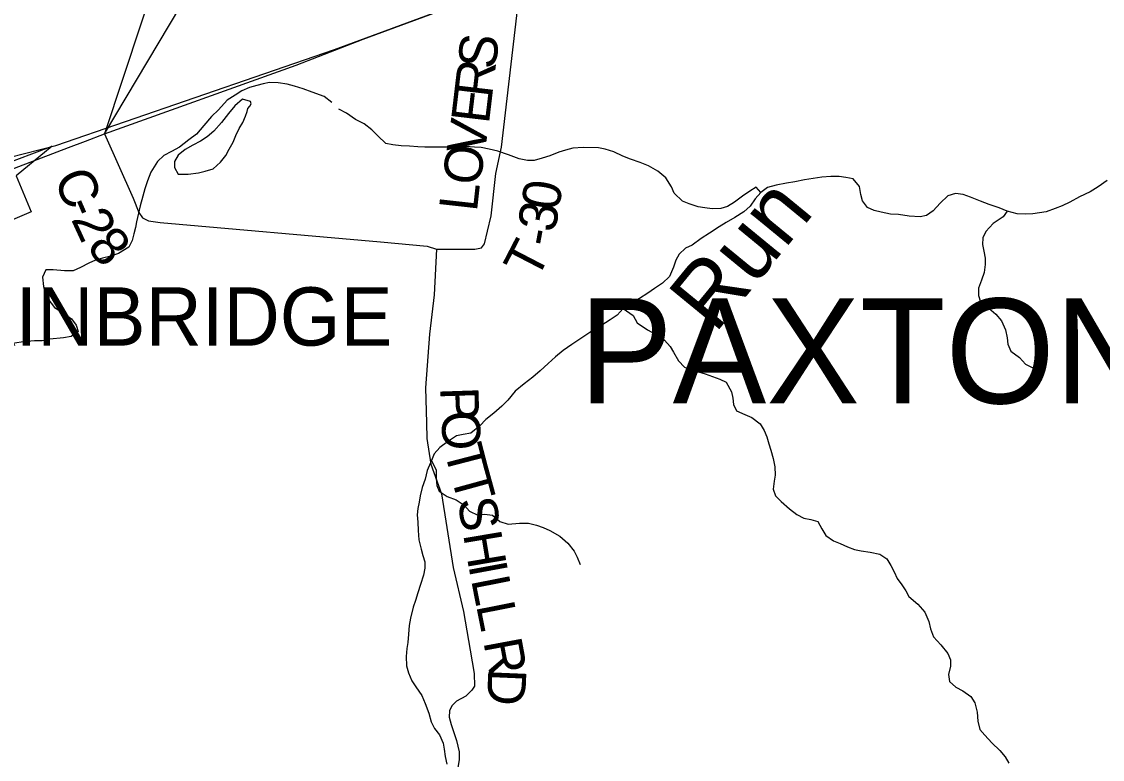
# Model space of a CAD drawing. Extents: x -139 to 835, y 0 to 440.
# Drawn here: x 494.5 to 550, y 270.4 to 308.2 of the extents above; entities that cross this region are included whole.
import ezdxf

# ---------------------------------------------------------------- set-up
doc = ezdxf.new("R2010")
doc.units = 0
for name, color, linetype in [('Default', 7, 'Continuous'), ('GM_X_Corporation', 7, 'Continuous'), ('GM_X_Corporation_Text', 7, 'Continuous'), ('GM_X_County_Road', 7, 'Continuous'), ('GM_X_County_Road_Text', 7, 'Continuous'), ('GM_X_Minor_Lake', 7, 'Continuous'), ('GM_X_Minor_River', 7, 'Continuous'), ('GM_X_Minor_River_Text', 7, 'Continuous'), ('GM_X_Rail_Line', 7, 'Continuous'), ('GM_X_Township_Road', 7, 'Continuous'), ('GM_X_Township_Road_Text', 7, 'Continuous'), ('GM_X_Township_Text', 7, 'Continuous'), ('GM_X_US_Route', 7, 'Continuous'), ('SH_Text', 7, 'Continuous')]:
    doc.layers.add(name, color=color, linetype=linetype)

msp = doc.modelspace()

# ---------------------------------------------------------------- linework, layer by layer
at = {"layer": 'Default'}
for p, q in [((497.834, 302.1), (498.811, 302.471)), ((496.955, 301.767), (497.834, 302.1)), ((493.599, 300.491), (496.955, 301.767))]:
    msp.add_line(p, q, dxfattribs=at)
at = {"layer": 'GM_X_Corporation'}
msp.add_lwpolyline([(493.37, 300.818), (496.112, 301.837), (494.271, 300.317), (495.033, 298.472), (493.952, 298.002)], dxfattribs=at)
at = {"layer": 'GM_X_County_Road'}
msp.add_lwpolyline([(498.811, 302.471), (500.28, 299.173), (500.561, 298.442), (500.748, 298.169), (501.061, 298.011), (501.655, 297.925), (512.976, 296.935), (515.364, 296.713), (515.847, 296.553), (515.739, 294.201), (515.498, 292.183), (515.283, 289.425), (515.341, 287.627), (515.357, 286.823), (515.564, 285.506), (516.106, 283.985), (516.712, 280.211), (517.237, 277.949), (517.588, 275.966), (517.785, 274.768), (517.796, 274.114), (517.665, 273.903), (517.533, 273.762), (517.357, 273.601), (516.886, 273.339), (516.634, 273.097), (516.524, 272.846), (516.502, 272.524), (516.601, 272.141), (516.886, 271.312), (517.013, 270.746), (517.013, 270.351), (516.925, 269.821)], dxfattribs=at)
at = {"layer": 'GM_X_Minor_Lake'}
for points in [[(506.3, 304.127), (505.897, 304.252), (505.501, 303.92), (505.169, 303.516), (504.81, 303.064), (504.425, 302.612), (504.081, 302.316), (503.739, 302.091), (503.344, 301.892), (502.949, 301.668), (502.593, 301.372), (502.405, 301.05), (502.401, 300.75), (502.592, 300.4), (503.102, 300.406), (503.625, 300.472), (503.979, 300.552), (504.385, 300.68), (504.768, 301.012), (505.035, 301.369), (505.209, 301.679), (505.41, 302.049), (505.545, 302.383), (505.72, 302.742), (505.907, 303.052), (506.042, 303.374)], [(506.042, 303.374), (506.126, 303.614), (506.163, 303.771), (506.26, 303.9), (506.334, 304.023), (506.3, 304.127)]]:
    msp.add_lwpolyline(points, dxfattribs=at)
at = {"layer": 'GM_X_Minor_River'}
for points in [[(510.478, 304.082), (510.091, 304.386), (509.467, 304.621), (509, 304.794), (508.557, 304.931), (508.18, 305.019), (507.724, 305.096), (507.28, 305.113), (506.953, 305.044), (506.625, 304.964), (506.245, 304.86), (505.851, 304.684), (505.508, 304.46), (505.1, 304.201), (504.649, 303.701), (504.305, 303.369), (503.907, 302.905), (503.522, 302.454), (503.139, 302.17), (502.651, 301.791), (502.243, 301.568), (501.848, 301.356), (501.531, 301.047), (501.183, 300.499), (501.008, 300.057), (500.871, 299.65), (500.775, 299.279), (500.637, 298.777), (500.554, 298.406), (500.443, 297.963), (500.4, 297.663), (500.304, 297.34), (500.221, 296.993), (500.059, 296.659), (499.519, 296.329), (499.126, 296.189), (498.707, 296.098), (498.339, 295.994), (497.998, 295.841), (497.564, 295.618), (497.196, 295.442), (496.752, 295.447), (496.165, 295.489), (495.799, 295.494), (495.624, 295.111), (495.67, 294.643), (495.757, 294.306), (495.896, 294.004), (496.23, 293.557), (496.683, 293.288), (497.109, 292.971), (497.34, 292.656), (497.453, 292.319), (497.084, 292.059), (496.691, 292.003), (495.998, 291.927), (495.605, 291.847), (495.213, 291.84), (494.625, 291.798), (494.206, 291.719)], [(532.5, 299.46), (532.269, 299.738), (531.941, 299.538), (531.56, 299.266), (531.152, 298.959), (530.797, 298.747), (530.457, 298.642), (530.014, 298.623), (529.623, 298.675), (529.285, 298.727), (528.831, 298.876), (528.481, 299.012), (528.056, 299.436), (527.917, 299.75), (527.636, 300.209), (527.224, 300.561), (526.745, 300.83), (526.317, 301.003), (525.811, 301.176), (525.422, 301.324), (524.956, 301.557), (524.514, 301.682), (524.176, 301.758), (523.382, 301.766), (522.847, 301.736), (522.481, 301.632), (522.127, 301.528), (521.669, 301.353), (521.276, 301.225), (520.871, 301.11), (520.532, 301.101), (520.103, 301.19), (519.545, 301.4), (519.001, 301.586), (518.559, 301.687), (518.143, 301.775), (517.804, 301.791), (517.361, 301.82), (516.971, 301.824), (516.54, 301.793), (516.071, 301.786), (515.693, 301.79), (515.25, 301.783), (514.885, 301.811), (514.469, 301.839), (514.039, 301.856), (513.609, 301.908), (513.245, 301.984), (512.833, 302.373), (512.525, 302.688), (512.138, 302.98), (511.697, 303.213), (511.232, 303.53), (510.844, 303.738)], [(550.297, 300.07), (549.824, 299.752), (549.416, 299.504), (548.866, 299.234), (548.367, 298.964), (547.974, 298.776), (547.62, 298.636), (547.162, 298.473), (546.822, 298.417), (546.47, 298.36), (546.078, 298.341), (545.675, 298.369), (545.155, 298.507), (544.74, 298.667), (544.234, 298.853), (543.793, 299.013), (543.275, 299.223), (542.899, 299.359), (542.508, 299.411), (542.116, 299.295), (541.707, 298.916), (541.35, 298.512), (541.021, 298.288), (540.695, 298.219), (540.122, 298.249), (539.575, 298.327), (539.159, 298.356), (538.69, 298.445), (538.327, 298.533), (537.977, 298.693), (537.721, 299.031), (537.647, 299.356), (537.574, 299.777), (537.24, 300.164), (536.863, 300.24), (536.525, 300.28), (536.095, 300.285), (535.638, 300.242), (534.75, 300.107), (534.254, 300.017), (533.823, 299.949), (533.287, 299.835), (532.856, 299.72), (532.5, 299.46), (532.223, 299.139), (531.957, 298.758), (531.628, 298.474), (531.168, 298.179), (530.721, 297.92), (530.367, 297.696), (529.867, 297.377), (529.447, 297.094), (528.973, 296.763), (528.645, 296.599), (528.316, 296.302), (528.142, 295.992), (528.02, 295.622), (527.819, 295.156), (527.462, 294.812), (527.042, 294.54), (526.7, 294.292), (526.267, 294.021), (525.859, 293.774), (525.439, 293.502), (525.122, 293.17), (524.767, 292.922), (524.294, 292.615), (523.874, 292.367), (523.414, 292.073), (522.796, 291.659), (522.349, 291.34), (521.967, 291.021), (521.584, 290.689), (521.175, 290.297), (520.806, 289.977), (520.359, 289.634), (519.885, 289.268), (519.514, 288.804), (519.211, 288.495), (518.789, 288.128), (518.381, 287.808), (518.077, 287.476), (517.616, 287.109), (517.224, 287.041), (516.884, 286.961), (516.424, 286.654), (516.03, 286.37), (515.739, 286.038), (515.591, 285.703), (515.376, 285.178), (515.266, 284.747)], [(545.155, 298.507), (544.943, 298.209), (544.43, 297.867), (544.06, 297.451), (543.913, 297.141), (543.895, 296.793), (543.956, 296.456), (544.029, 296.084), (544.025, 295.772), (543.968, 295.352), (543.833, 294.958), (543.684, 294.552), (543.679, 294.168), (543.792, 293.843), (544.205, 293.526), (544.579, 293.222), (544.861, 292.871), (545.064, 292.401), (545.15, 292.004), (545.185, 291.668), (545.337, 291.319), (545.789, 290.99), (546.097, 290.651), (546.615, 290.381), (546.952, 290.221)], [(525.439, 293.502), (525.942, 293.137), (526.159, 292.763), (526.689, 292.409), (527.129, 292.164), (527.555, 291.884), (527.851, 291.556), (528.029, 291.255), (528.285, 290.82), (528.58, 290.493), (528.969, 290.345), (529.307, 290.257), (529.644, 290.157), (530.021, 290.021), (530.397, 289.873), (530.733, 289.714), (531.001, 289.231), (531.062, 288.906), (531.097, 288.57), (531.249, 288.256), (531.69, 288.06), (532.039, 287.912), (532.465, 287.583), (532.682, 287.233), (532.822, 286.908), (532.921, 286.547), (533.021, 286.234), (533.133, 285.801), (533.219, 285.368), (533.24, 284.948), (533.196, 284.636), (533.139, 284.229), (533.265, 283.892), (533.548, 283.589), (533.986, 283.224), (534.347, 282.932), (534.71, 282.736), (535.074, 282.672), (535.437, 282.561), (535.641, 282.186), (535.845, 281.848), (536.233, 281.58), (536.583, 281.432), (536.959, 281.272), (537.322, 281.137), (537.66, 281.061), (538.128, 280.996), (538.609, 280.895), (538.971, 280.651), (539.175, 280.313), (539.353, 279.987), (539.505, 279.637), (539.748, 279.311), (539.953, 279.009), (540.106, 278.707), (540.57, 278.318), (540.93, 277.918), (541.132, 277.424), (541.218, 277.051), (541.369, 276.642), (541.755, 276.23), (542.114, 275.794), (542.24, 275.469), (542.249, 275.145), (542.139, 274.702), (542.187, 274.354), (542.522, 274.062), (542.871, 273.866), (543.285, 273.574), (543.489, 273.248), (543.613, 272.767), (543.646, 272.31), (543.745, 271.89), (544.002, 271.587), (544.375, 271.199), (544.774, 270.799), (545.044, 270.484), (545.235, 270.158)], [(515.591, 285.703), (515.832, 285.209), (515.827, 284.777), (515.861, 284.417), (515.988, 284.116), (516.401, 283.859), (516.868, 283.686), (517.269, 283.406), (517.539, 283.103), (517.966, 282.894), (518.318, 282.938), (518.735, 282.886), (519.096, 282.57), (519.537, 282.433), (520.111, 282.487), (520.567, 282.482), (520.983, 282.382), (521.333, 282.258), (521.67, 282.098), (522.187, 281.817), (522.6, 281.452), (522.92, 281.041), (523.073, 280.739), (523.237, 280.366)], [(515.266, 284.747), (515.117, 284.317), (515.02, 283.886), (514.964, 283.551), (514.895, 283.24), (514.865, 282.916), (514.886, 282.532), (514.906, 282.1), (514.952, 281.631), (515.063, 281.138), (515.151, 280.826), (515.251, 280.501), (515.259, 280.165), (515.19, 279.817), (515.027, 279.339), (514.891, 278.909), (514.769, 278.514), (514.66, 278.168), (514.51, 277.605), (514.453, 277.234), (514.408, 276.779), (514.376, 276.347), (514.333, 276.048), (514.302, 275.628), (514.309, 275.16), (514.422, 274.799), (514.586, 274.378), (514.79, 274.075), (515.097, 273.628), (515.275, 273.218), (515.451, 272.725), (515.575, 272.279), (515.741, 271.942), (515.997, 271.615), (516.187, 271.181), (516.248, 270.869), (516.295, 270.496), (516.382, 270.111)]]:
    msp.add_lwpolyline(points, dxfattribs=at)
at = {"layer": 'GM_X_Rail_Line'}
msp.add_lwpolyline([(461.72, 306.518), (463.204, 305.984), (481.829, 301.388), (483.589, 301.041), (485.626, 300.734), (487.707, 300.627), (489.642, 300.667), (491.519, 300.827), (493.891, 301.254), (496.306, 301.869), (510.606, 306.801), (564.86, 326.817)], dxfattribs=at)
at = {"layer": 'GM_X_Township_Road'}
msp.add_lwpolyline([(515.847, 296.553), (517.823, 296.547), (518.16, 296.621), (518.309, 296.819), (518.476, 297.476), (518.664, 298.264), (518.905, 300.443), (519.182, 301.788), (520.178, 310.331)], dxfattribs=at)
at = {"layer": 'GM_X_US_Route'}
for points in [[(497.834, 302.1), (498.811, 302.471), (508.647, 305.997), (512.08, 307.344), (516.823, 309.075), (520.178, 310.331), (531.308, 314.514), (540.741, 317.927), (549.297, 321.159), (555.655, 323.421)], [(493.599, 300.491), (496.955, 301.767), (497.834, 302.1)]]:
    msp.add_lwpolyline(points, dxfattribs=at)
at = {"layer": 'SH_Text'}
msp.add_lwpolyline([(498.811, 302.471), (508.23, 318.313), (508.3, 331.165)], close=True, dxfattribs=at)

# ---------------------------------------------------------------- texts
at = {"layer": 'GM_X_Corporation_Text'}
msp.add_text('BAINBRIDGE', height=2.9942, rotation=0, dxfattribs=at).set_placement((488.893, 291.598))
at = {"layer": 'GM_X_County_Road_Text'}
for s, height, rotation, p in [('C', 1.975, 293.1105, (496.164, 300.207)), ('2', 1.977, 294.697, (497.068, 298.1)), ('-', 1.976, 293.395, (496.754, 298.824)), ('8', 1.984, 310.9243, (497.833, 296.622)), ('P', 1.958, 271.9061, (516.042, 289.454)), ('O', 1.959, 273.2014, (516.084, 288.202)), ('T', 1.966, 284.5358, (516.228, 286.269)), ('T', 1.967, 285.3661, (516.574, 284.936)), ('S', 1.962, 279.5584, (516.922, 283.677)), ('H', 1.962, 279.5787, (517.213, 281.92)), ('I', 1.962, 280.4939, (517.482, 280.329)), ('L', 1.963, 281.1437, (517.621, 279.582)), ('L', 1.963, 281.2676, (517.882, 278.256)), ('R', 1.963, 280.5866, (518.253, 276.395)), ('D', 1.958, 267.5855, (518.517, 275.039))]:
    msp.add_text(s, height=height, rotation=rotation, dxfattribs=at).set_placement(p)
at = {"layer": 'GM_X_Minor_River_Text'}
msp.add_text('Run', height=3.3084, rotation=50.6016, dxfattribs=at).set_placement((530.143, 292.163))
at = {"layer": 'GM_X_Township_Road_Text'}
for s, height, rotation, p in [('S', 1.96, 83.228, (518.873, 305.748)), ('R', 1.96, 83.2301, (518.698, 304.281)), ('E', 1.96, 83.1947, (518.539, 302.944)), ('V', 1.961, 81.768, (518.306, 301.332)), ('O', 1.961, 81.4822, (518.07, 299.757)), ('L', 1.96, 83.6164, (517.923, 298.437)), ('0', 1.961, 81.1478, (522.126, 298.485)), ('3', 1.962, 80.063, (521.929, 297.359)), ('-', 1.962, 79.4661, (521.791, 296.613)), ('T', 1.98, 62.6031, (520.985, 294.887))]:
    msp.add_text(s, height=height, rotation=rotation, dxfattribs=at).set_placement(p)
at = {"layer": 'GM_X_Township_Text'}
msp.add_text('PAXTON', height=5.3895, rotation=0, dxfattribs=at).set_placement((523.171, 288.63))

doc.saveas('drawing.dxf')
